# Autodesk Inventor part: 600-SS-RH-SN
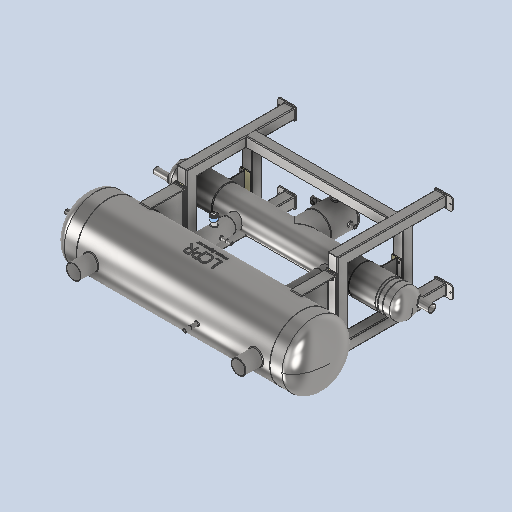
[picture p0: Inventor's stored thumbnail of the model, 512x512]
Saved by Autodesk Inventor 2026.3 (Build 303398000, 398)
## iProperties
Created: 2026-05
Part Number: 600-SS-RH-SN
Material: Generic
Document SubType Name: Modeling
Designer: rva
Density: 1 g/cm^3
Appearance: Default
Author: rva
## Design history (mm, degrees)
derived "LCPR-SS-600-FULL-ASSEMBLY-RH-SN.iam"
body "Solid1"
node "LCPR-SS-600-FULL FRAME ASSEMBLY.iam:1::LCPR-SS-600-FRAME ASS"
node "LCPR-SS-600-1840-125-SN-WELD.iam:1::600 mm Dome End Cap.ipt:"
node "LCPR-SS-600-1840-125-SN-WELD.iam:1::600 mm Dome End Cap.ipt:"
node "LCPR-SS-600-1840-125-SN-WELD.iam:1::LPR-600-Leg Assembly.iam"
node "LCPR-SS-600-1840-125-SN-WELD.iam:1::LPR-600-Leg Assembly.iam"
node "LCPR-SS-600-1840-125-SN-WELD.iam:1::H1100-R.ipt:1"
node "LCPR-SS-600-1840-125-SN-WELD.iam:1::LCPR-LOGO.ipt:1"
node "LCPR-SS-600-1840-125-SN-WELD.iam:1::Welds"
node "Sub-SS-250-125-1813-52-65-50-RH.iam:1::SS-LCPR-250 Blank Pla"
node "Sub-SS-250-125-1813-52-65-50-RH.iam:1::SS-250-52 hole Sub Co"
node "Sub-SS-250-125-1813-52-65-50-RH.iam:1::SS-250-52 hole Sub Co"
node "Sub-SS-250-125-1813-52-65-50-RH.iam:1::SS-250 mm Subcooler L"
node "Sub-SS-250-125-1813-52-65-50-RH.iam:1::SS-250 mm Subcooler L"
node "Sub-SS-250-125-1813-52-65-50-RH.iam:1::DIN 2462 Tube 10 x 1 "
node "Sub-SS-250-125-1813-52-65-50-RH.iam:1::DIN 2462 Tube 10 x 1 "
node "Sub-SS-250-125-1813-52-65-50-RH.iam:1::DIN 2462 Tube 10 x 1 "
node "Sub-SS-250-125-1813-52-65-50-RH.iam:1::DIN 2462 Tube 10 x 1 "
node "Sub-SS-250-125-1813-52-65-50-RH.iam:1::DIN 2462 Tube 10 x 1 "
node "Sub-SS-250-125-1813-52-65-50-RH.iam:1::DIN 2462 Tube 10 x 1 "
node "Sub-SS-250-125-1813-52-65-50-RH.iam:1::DIN 2462 Tube 10 x 1 "
node "Sub-SS-250-125-1813-52-65-50-RH.iam:1::DIN 2462 Tube 10 x 1 "
node "Sub-SS-250-125-1813-52-65-50-RH.iam:1::DIN 2462 Tube 10 x 1 "
node "Sub-SS-250-125-1813-52-65-50-RH.iam:1::DIN 2462 Tube 10 x 1 "
node "Sub-SS-250-125-1813-52-65-50-RH.iam:1::DIN 2462 Tube 10 x 1 "
node "Sub-SS-250-125-1813-52-65-50-RH.iam:1::DIN 2462 Tube 10 x 1 "
node "Sub-SS-250-125-1813-52-65-50-RH.iam:1::DIN 2462 Tube 10 x 1 "
node "Sub-SS-250-125-1813-52-65-50-RH.iam:1::DIN 2462 Tube 10 x 1 "
node "Sub-SS-250-125-1813-52-65-50-RH.iam:1::H1100-R.ipt:1"
node "Sub-SS-250-125-1813-52-65-50-RH.iam:1::H1100-R.ipt:2"
node "Sub-SS-250-125-1813-52-65-50-RH.iam:1::1-2 Inch NPT Socket -"
node "Sub-SS-250-125-1813-52-65-50-RH.iam:1::1-2 Inch NPT Socket -"
node "Sub-SS-250-125-1813-52-65-50-RH.iam:1::3-4 Inch NPT Socket -"
node "Sub-SS-250-125-1813-52-65-50-RH.iam:1::Welds"
node "AS 1111 - Metric M8 x 130:1"
node "AS 1111 - Metric M8 x 130:2"
node "AS 1111 - Metric M8 x 130:3"
node "AS 1111 - Metric M8 x 130:4"
node "AS 1111 - Metric M10 x 130:1"
node "AS 1111 - Metric M10 x 130:2"
node "AS 1111 - Metric M10 x 130:3"
node "AS 1111 - Metric M10 x 130:4"
node "AS 1112 (4) - Metric M10:1"
node "AS 1112 (4) - Metric M10:2"
node "AS 1112 (4) - Metric M10:3"
node "AS 1112 (4) - Metric M10:4"
node "AS 1112 (4) - Metric M8:1"
node "AS 1112 (4) - Metric M8:2"
node "AS 1112 (4) - Metric M8:3"
node "AS 1112 (4) - Metric M8:4"
node "AS 1237 (4.1) 8 mm:1"
node "AS 1237 (4.1) 8 mm:2"
node "AS 1237 (4.1) 8 mm:3"
node "AS 1237 (4.1) 8 mm:4"
node "AS 1237 (4.1) 8 mm:5"
node "AS 1237 (4.1) 8 mm:6"
node "AS 1237 (4.1) 8 mm:7"
node "AS 1237 (4.1) 8 mm:8"
node "AS 1237 (4.1) 10 mm:1"
node "AS 1237 (4.1) 10 mm:2"
node "AS 1237 (4.1) 10 mm:3"
node "AS 1237 (4.1) 10 mm:4"
node "AS 1237 (4.1) 10 mm:5"
node "AS 1237 (4.1) 10 mm:6"
node "AS 1237 (4.1) 10 mm:7"
node "AS 1237 (4.1) 10 mm:8"
node "Nylon Heat Tranfer Spacer 568x100.ipt:1"
node "Nylon Heat Tranfer Spacer 568x100.ipt:2"
node "Nylon Heat Tranfer Spacer 175x100.ipt:1"
node "Nylon Heat Tranfer Spacer 175x100.ipt:2"
node "Welds"
node "LCPR-SS-600-FULL-ASSEMBLY-RH-SN.iam_Bodies"
